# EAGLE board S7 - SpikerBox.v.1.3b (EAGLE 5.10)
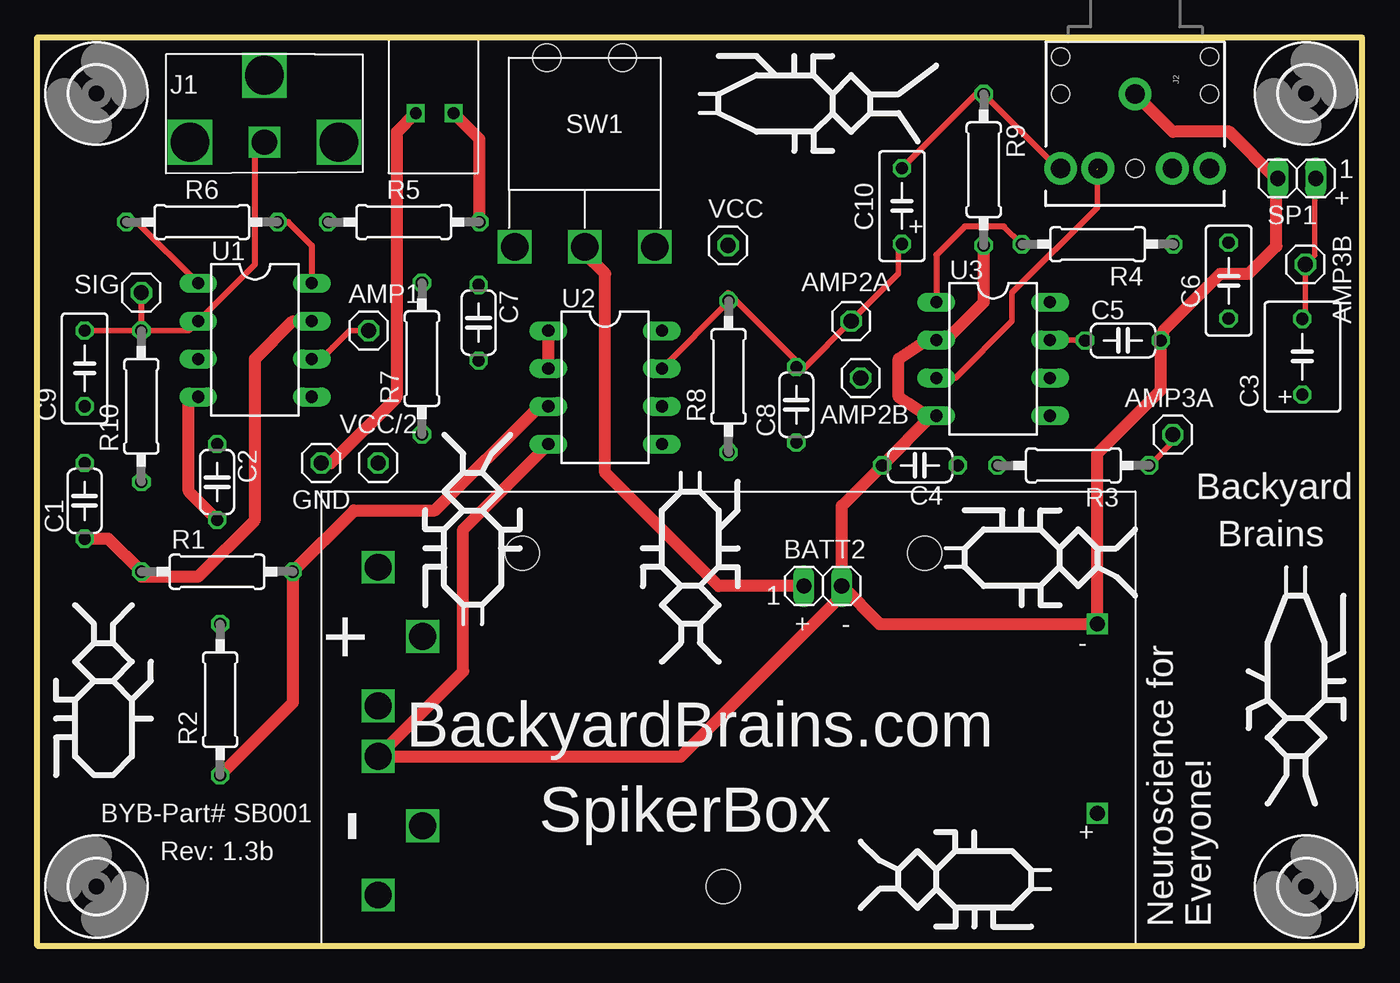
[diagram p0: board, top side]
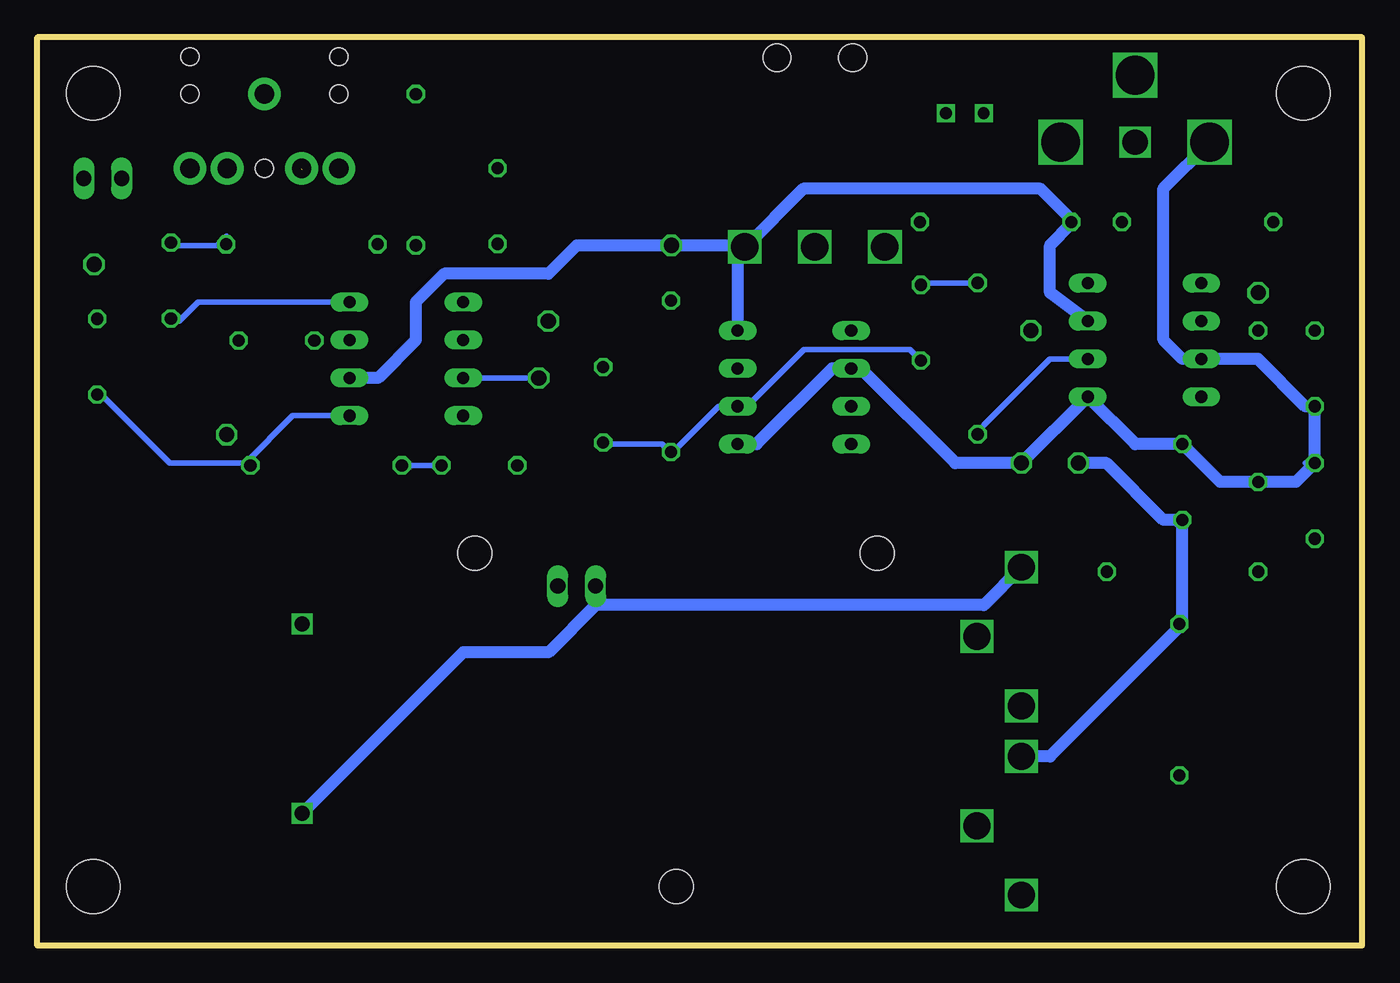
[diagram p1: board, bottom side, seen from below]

Size 88.9 x 60.96 mm. Coordinates in mm from the lower left corner, seen from the top.
Outline: 0,0 0,60.96 88.9,60.96 88.9,0 0,0
Copper layers (1*16): Top 0.035mm / dielectric 1.5mm / Bottom 0.035mm
Design rules "PCB-POOL *": minimum track width 15mil, minimum drill 12mil, track to track 15mil, track to pad 15mil, pad to pad 15mil, via to via 15mil, smd to smd 15mil, copper to edge 20mil, drill to drill 8mil, minimum pad ring 8mil, minimum via ring 6mil, stop-mask expansion 3mil, vias tented up to drill 0mil, thermal gap 8mil

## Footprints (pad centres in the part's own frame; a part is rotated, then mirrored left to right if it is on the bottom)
1X01 = drill 1.016 octagon: 1 0,0
KEYSTONE-593-594 = drill 1.8 square: +9V$1 -12.7,0; +9V$2 -8.05,3; +9V$3 -3.4,0; GND$1 0,0; GND$2 4.65,3; GND$3 9.3,0
1X02 = drill 1.016 long: 1 -1.27,0; 2 1.27,0
BH9VPC = drill 1.016 square: 9V 0,0; GND 0,12.7 | hole 2.286: -11.582,17.45; -38.57,17.44; -25.09,-4.91
C050-024X044 = drill 0.813 octagon: 1 -2.54,0; 2 2.54,0
C050-050X075 = drill 0.813 octagon: 1 -2.54,0; 2 2.54,0
C050-030X075 = drill 0.813 octagon: 1 -2.54,0; 2 2.54,0
3,6 = hole 3.6: 0,0
RCJ = drill 2.6 square: GND$1 -5,-4.5; GND$2 0,0; GND$3 5,-4.5 | drill 1.7 square: SIG 0,-4.5
AUDIO-JACK = drill 1.3 pad 2.184 round: 1 0,0; 2 5,-5; 3 5,5; 4 5,-2.5; 5 5,2.5 | hole 1.2: 0,5; -2.5,5; -2.5,-5; 0,-5; 5,0
SSF-LXH104GD = drill 0.8 square: ANODE 5.1,1.27; CATHODE 5.1,-1.27
0207/10 = drill 0.813 octagon: 1 -5.08,0; 2 5.08,0
2M1-SP1-T2-B4-M6RE = drill 1.85 square: P1 0,-4.7; P2 0,0; P3 0,4.7 | hole 1.85: -12.7,2.54; -12.7,-2.54
DIL08 = drill 0.813 pad 1.27 long: 1 -3.81,-3.81; 2 -1.27,-3.81; 3 1.27,-3.81; 4 3.81,-3.81; 5 3.81,3.81; 6 1.27,3.81; 7 -1.27,3.81; 8 -3.81,3.81

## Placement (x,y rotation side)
AMP1  AMP1  [1X01]  22.23,41.27 0 top
AMP2A  AMP2  [1X01]  54.61,41.91 90 top
AMP2B  AMP2  [1X01]  55.24,38.1 180 top
AMP3A  AMP3A  [1X01]  76.2,34.29 0 top
AMP3B  AMP3B  [1X01]  85.09,45.72 270 top
BATT1  9V-BATT-HOLDERSTANDS  [KEYSTONE-593-594]  22.86,12.7 270 top
BATT2  9V-BATT-HOLDERHEADERS  [1X02]  52.7,24.13 0 top
BATT3  9V-BATT-HOLDERBH9VPC  [BH9VPC]  71.12,8.89 0 top
C1  0.22uF  [C050-024X044]  3.17,29.84 90 top
C2  0.22uF  [C050-024X044]  12.06,31.11 270 top
C3  220uF  [C050-050X075]  84.89,39.52 90 top
C4  0.047uF  [C050-024X044]  59.23,32.23 180 top
C5  0.1uF  [C050-024X044]  72.85,40.61 0 top
C6  10uF  [C050-030X075]  79.93,44.63 270 top
C7  0.47uF  [C050-024X044]  29.62,41.81 270 top
C8  560pF  [C050-024X044]  50.93,36.3 90 top
C9  10uF  [C050-030X075]  3.17,38.73 90 top
C10  10uF  [C050-030X075]  58.01,49.63 90 top
GND  GND  [1X01]  19.05,32.38 180 top
H1  MOUNT-HOLE3.6  [3,6]  85.14,57.2 0 top
H2  MOUNT-HOLE3.6  [3,6]  3.96,57.2 0 top
H3  MOUNT-HOLE3.6  [3,6]  85.14,3.96 0 top
H4  MOUNT-HOLE3.6  [3,6]  3.96,3.96 90 top
J1  RCA  [RCJ]  15.24,58.42 0 top
J2  AUD  [AUDIO-JACK]  73.66,57.15 270 top
LED2  LEDSSF-LXH104GD  [SSF-LXH104GD]  26.67,60.96 270 top
R1  10k  [0207/10]  12.06,25.1 0 top
R2  10k  [0207/10]  12.27,16.51 90 top
R3  10  [0207/10]  69.52,32.23 180 top
R4  0  [0207/10]  71.15,47.07 180 top
R5  390  [0207/10]  24.59,48.56 0 top
R6  68K  [0207/10]  11.05,48.56 0 top
R7  1k  [0207/10]  25.81,39.4 90 top
R8  220k  [0207/10]  46.38,38.2 90 top
R9  10K  [0207/10]  63.5,52.07 270 top
R10  100k  [0207/10]  6.99,36.2 90 top
SIG  SIG  [1X01]  6.99,43.81 270 top
SP1  SPEAKER  [1X02]  84.51,51.49 180 top
SW1  SPDT Switch  [2M1-SP1-T2-B4-M6RE]  36.73,46.89 270 top
U1  AD623N  [DIL08]  14.61,40.64 270 top
U2  TLC2272344P  [DIL08]  38.1,37.47 270 top
U3  LM386N-1  [DIL08]  64.14,39.37 270 top
VCC  VCC  [1X01]  46.35,46.99 0 top
VCC/2  VCC/2  [1X01]  22.86,32.38 180 top

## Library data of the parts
AMP1 AMP2A AMP2B AMP3A AMP3B GND SIG VCC VCC/2 = pinhead
BATT1 = byb; DIGIKEY: 593K-ND, 594K-ND; MANUFACTURER: KEYSTONE ELECTRONICS; PARTNO: 593,594
BATT2 = byb; DIGIKEY: N145-ND; MANUFACTURER: ENERGIZER BATTERY COMPANY; PARTNO: EN22
BATT3 = byb; DIGIKEY: BH9V-PC-ND; MANUFACTURER: MEMORY PROTECTION DEVICES; PARTNO: BH9V-PC
C1 C2 = resistor; DIGIKEY: P986-ND; MANUFACTURER: Panasonic - ECG; PARTNO: ECE-A1HKSR22
C3 = resistor; DIGIKEY: 565-1674-ND; MANUFACTURER: UNITED CHEMI-CON; PARTNO: EKZE250ELL221MHB5D
C4 = resistor; DIGIKEY: BC1099CT-ND; MANUFACTURER: VISHAY/BC COMPONENTS; PARTNO: K473K15X7RF5TH5
C5 = resistor; DIGIKEY: BC1148CT-ND; MANUFACTURER: Vishay/BC Components; PARTNO: K104Z15Y5VE5TL2
C6 C9 C10 = resistor; DIGIKEY: P966-ND; MANUFACTURER: Panasonic - ECG; PARTNO: ECE-A1CKS100
C7 = resistor; DIGIKEY: BC1150CT-ND; MANUFACTURER: Vishay/BC Components; PARTNO: K474Z20Y5VE5TL2
C8 = resistor; DIGIKEY: BC1022CT-ND; MANUFACTURER: Vishay/BC Components; PARTNO: K561J15C0GF5TL2
H1-H4 = holes
J1 = byb; DIGIKEY: CP-1403-ND; MANUFACTURER: CUI Inc; PARTNO: RCJ-014
J2 = byb; DIGIKEY: CP1-3524NG-ND; MANUFACTURER: CUI Inc; PARTNO: SJ1-3524NG
LED2 = byb; DIGIKEY: 67-1037-ND; MANUFACTURER: LUMEX OPTO/COMPONENTS INC; PARTNO: SSF-LXH104GD
R1 R2 R9 = rcl; DIGIKEY: P10KBACT-ND; MANUFACTURER: Panasonic - ECG; PARTNO: ERD-S2TJ103V
R3 = rcl; DIGIKEY: P10BACT-ND; MANUFACTURER: Panasonic - ECG; PARTNO: ERD-S2TJ100V
R4 = rcl; DIGIKEY: CD14ZT0R00CT-ND; MANUFACTURER: Stackpole Electronics; PARTNO: CD14ZT0R00
R5 = rcl; DIGIKEY: CF14JT390RCT-ND; MANUFACTURER: Stackpole Electronics; PARTNO: CF14JT390R
R6 = rcl; DIGIKEY: P68KBACT-ND; MANUFACTURER: Panasonic - ECG; PARTNO: ERD-S2TJ683V
R7 = rcl; DIGIKEY: P1.0KBACT-ND; MANUFACTURER: Panasonic - ECG; PARTNO: ERD-S2TJ102V
R8 = rcl; DIGIKEY: P220KCACT-ND; MANUFACTURER: Panasonic - ECG; PARTNO: ERO-S2PHF2203
R10 = rcl; DIGIKEY: P100KBACT-ND; MANUFACTURER: Panasonic - ECG; PARTNO: ERD-S2TJ104V
SP1 = byb; DIGIKEY: 102-1554-ND; MANUFACTURER: CUI Inc; PARTNO: CLS0271M-L152
SW1 = byb; DIGIKEY: 432-1164-ND; MANUFACTURER: Carling Technologies; PARTNO: 2M1-SP1-T2-B4-M6RE
U1 = byb; DIGIKEY: AD623ANZ-ND; MANUFACTURER: ANALOG DEVICES INC; PARTNO: AD623ANZ
U2 = byb; DIGIKEY: 296-1812-5-ND; MANUFACTURER: TEXAS INSTRUMENTS; PARTNO: TLC2272CP
U3 = byb; DIGIKEY: LM386N-3-ND; MANUFACTURER: NATIONAL SEMICONDUCTOR; PARTNO: LM386N-3/NOPB

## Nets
GND: BATT1.GND$1 BATT2.2 BATT3.GND C2.2 C4.2 C5.2 GND.1 J2.1 LED2.CATHODE R2.2 R9.2 SP1.2 U1.4 U2.4 U3.2 U3.4
IN-: C9.2 J1.SIG R10.2 SIG.1 U1.2
N$2: AMP3B.1 C3.2 SP1.1
N$3: AMP1.1 R7.1 U1.6
N$4: C10.2 J2.2 R9.1
N$6: C4.1 R3.2
N$7: AMP3A.1 C3.1 R3.1 U3.5
N$8: C5.1 U3.7
N$10: C6.1 R4.1
N$11: R4.2 U3.1
N$12: C6.2 U3.8
N$14: LED2.ANODE R5.2
N$15: R6.1 U1.1
N$18: R6.2 U1.8
N$19: C7.1 R7.2
N$20: C7.2 C8.1 R8.1 U2.6
N$24: R1.2 R2.1 U2.3
N$28: AMP2B.1 J2.4 U3.3
N$29: AMP2A.1 C8.2 C10.1 R8.2 U2.7
V9HOT: BATT1.+9V$1 BATT2.1 BATT3.9V SW1.P2
VCC: C1.1 R1.1 R5.1 SW1.P3 U1.7 U2.8 U3.6 VCC.1
VCC/2: C1.2 C2.1 C9.1 J1.GND$1 R10.1 U1.3 U1.5 U2.1 U2.2 U2.5 VCC/2.1

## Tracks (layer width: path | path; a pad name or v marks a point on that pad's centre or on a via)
GND
  Top 0.813: BATT2.2 53.98,29.52 C4.2 60.02,35.56 U3.4 59.69,35.56 57.78,36.83 57.78,39.37 59.69,40.64 U3.2 60.96,40.64 63.5,43.18 R9.2 | 83.13,51.49 SP1.2 | 83.13,51.49 80.01,54.61 76.2,54.61 J2.1 | 83.13,51.49 83.13,46.94 81.28,45.09 79.38,45.09 75.56,41.27 75.56,40.79 C5.2 75.39,37.29 71.12,33.02 BATT3.GND 56.52,21.59 BATT2.2 | C2.2 10.16,30.48 10.16,36.83 U1.4 | LED2.CATHODE 24.13,54.59 24.13,36.83 19.68,32.38 GND.1 | BATT2.2 53.98,23.5 43.18,12.7 BATT1.GND$1 28.57,18.41 28.57,27.94 U2.4
  Bottom 0.381: 12.7,21.59 12.06,22.23 C2.2
  Bottom 0.813: C2.2 12.27,28.37 | BATT1.GND$1 20.95,12.7 12.06,21.59 | R2.2 12.06,21.59 | 12.06,21.59 C2.2 | GND.1 17.14,32.38 13.34,28.57 C2.2
IN-
  Top 0.381: C9.2 R10.2 10.16,41.27 U1.2
  Top 0.406: J1.SIG 14.55,53.28 14.61,53.34 14.61,45.72 U1.2 | SIG.1 R10.2
N$2
  Top 0.381: C3.2 85.09,42.55 AMP3B.1 85.72,46.35 85.72,51.44 SP1.1
N$3
  Top 0.381: AMP1.1 20.95,41.27 19.05,39.37 U1.6
  Bottom 0.381: U1.6 20.95,39.37 25.4,34.92 R7.1
N$4
  Top 0.381: R9.1 68.58,52.07 J2.2
  Top 0.406: C10.2 62.99,57.15 R9.1
N$6
  Bottom 0.381: C4.1 R3.2
N$7
  Top 0.406: AMP3A.1 76.2,33.83 R3.1
  Bottom 0.381: 74.93,32.38 71.75,35.56 U3.5 | 74.93,32.38 80.01,32.38 84.45,36.83 C3.1 | 74.93,32.38 R3.1
N$8
  Top 0.381: U3.7 69.85,40.64 C5.1
N$10
  Bottom 0.381: R4.1 76.2,47.62 76.83,46.99 79.38,46.99 C6.1
N$11
  Top 0.406: R4.2 64.87,48.26 62.23,48.26 60.33,46.35 U3.1
N$12
  Bottom 0.381: U3.8 78.11,43.18 79.38,41.91 C6.2
N$14
  Top 0.813: R5.2 29.67,54.13 LED2.ANODE
N$15
  Top 0.406: R6.1 6.68,48.56 U1.1
N$18
  Top 0.406: R6.2 16.84,48.56 18.41,46.99 U1.8
N$19
  Bottom 0.381: R7.2 29.18,44.48 29.84,44.45 29.74,44.35 C7.1
N$20
  Bottom 0.381: 46.35,33.02 43.18,36.2 U2.6 41.27,36.2 37.47,40.01 30.35,40.01 C7.2 | 46.35,33.02 46.99,33.66 50.8,33.66 C8.1 | 46.35,33.02 R8.1
N$24
  Top 0.813: U2.3 33.66,36.2 26.67,29.21 21.26,29.21 R1.2 17.14,16.31 R2.1
N$28  (1 unrouted)
  Top 0.381: U3.3 61.59,38.1 65.41,41.91 65.41,43.81 71.12,49.53 71.12,52.07
  Bottom 0.381: AMP2B.1 U3.3
N$29
  Top 0.381: U2.7 46.35,43.18 R8.2 46.35,43.81 50.8,39.37 C8.2 51.44,38.73 AMP2A.1 57.78,45.09 57.78,46.86 C10.1
V9HOT
  Top 0.813: SW1.P2 36.73,46.46 38.1,45.09 38.1,31.75 45.72,24.13 BATT2.1
  Bottom 0.813: BATT3.9V 60.33,19.68 54.61,19.68 51.44,22.86 | 51.44,22.86 BATT2.1 | BATT1.+9V$1 25.4,22.86 51.44,22.86
VCC
  Top 0.813: U1.7 17.14,41.91 14.61,39.37 14.61,28.57 10.79,24.77 6.99,24.77 R1.1 4.78,27.3 C1.1
  Bottom 0.813: U2.8 41.91,46.99 41.81,46.89 SW1.P3 | SW1.P3 41.53,46.99 VCC.1 52.7,46.99 54.61,45.09 61.59,45.09 63.5,43.18 63.5,40.64 66.04,38.1 U3.6 | SW1.P3 37.52,50.8 21.59,50.8 19.51,48.72 R5.1 19.51,48.44 20.95,46.99 20.95,43.81 U1.7
VCC/2
  Top 0.813: U2.2 U2.1
  Bottom 0.381: C1.2 3.81,32.38
  Bottom 0.813: U2.5 40.64,33.66 35.56,38.73 U2.2 33.66,38.73 27.3,32.38 VCC/2.1 U1.5 15.24,33.66 C2.1 9.53,31.11 R10.1 4.45,31.11 C1.2 C9.1 3.81,36.2 6.99,39.37 U1.3 12.06,39.37 13.34,40.64 13.34,50.83 J1.GND$1

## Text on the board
tPlace: + | + | + | Backyard | Brains | + | - | - | BackyardBrains.com | BYB-Part# SB001 | SpikerBox | + | Rev: 1.3b | Neuroscience for | Everyone!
